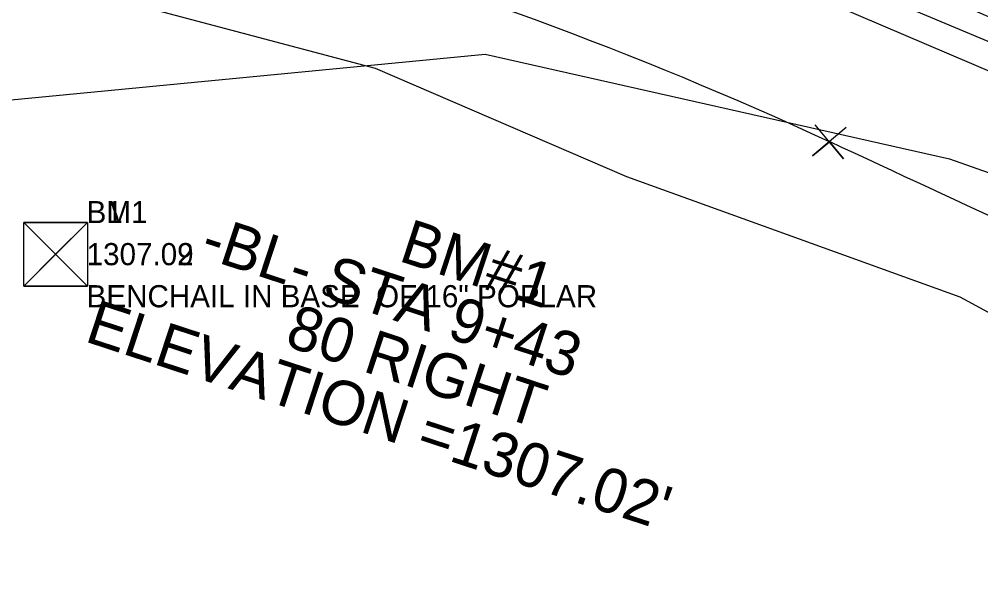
# Model space of a CAD drawing. Extents: x 1234385 to 1237843, y 694759 to 696635.
# Drawn here: x 1235013.1 to 1235121.7, y 695194.5 to 695257.9 of the extents above; entities that cross this region are included whole.
import ezdxf

# ---------------------------------------------------------------- set-up
doc = ezdxf.new("R2010")
doc.units = 0
for name, color, linetype in [('CTL Sheet Text', 7, 'Continuous'), ('CTL Vertical Benchmark CELL', 7, 'Continuous'), ('CTL Vertical Benchmark Cogo Comment', 7, 'Continuous'), ('CTL Vertical Benchmark Cogo Elevation', 7, 'Continuous'), ('CTL Vertical Benchmark Cogo Number', 7, 'Continuous'), ('Exist Horizontal Alignment', 7, 'Continuous'), ('Exist Hydro Jurisdictional Stream or Body of Water', 7, 'Continuous'), ('Exist Property Corner CELL', 7, 'Continuous'), ('Exist Right of Way Line', 7, 'Continuous'), ('Exist Roads EOP', 7, 'Continuous'), ('Exist Utilities Telephone UG Cable SUE LOS C', 7, 'Continuous'), ('Exist Vegetation Woods Line', 7, 'Continuous')]:
    doc.layers.add(name, color=color, linetype=linetype)

msp = doc.modelspace()

# ---------------------------------------------------------------- linework, layer by layer
at = {"layer": 'CTL Vertical Benchmark CELL'}
msp.add_line((1235017.19, 695231.36), (1235017.19, 695231.36), dxfattribs=at)
msp.add_line((1235017.19, 695231.36), (1235017.19, 695231.36), dxfattribs=at)
msp.add_lwpolyline([(1235013.59, 695234.95), (1235020.78, 695234.95), (1235020.78, 695227.76), (1235013.59, 695227.76)], close=True, dxfattribs=at)
msp.add_lwpolyline([(1235013.59, 695234.95), (1235020.78, 695234.95), (1235020.78, 695227.76), (1235013.59, 695227.76)], close=True, dxfattribs=at)
for points in [[(1235020.78, 695234.95), (1235013.59, 695227.76), (1235017.19, 695231.35), (1235020.78, 695227.76), (1235013.59, 695234.95)], [(1235017.19, 695231.35), (1235020.78, 695234.95), (1235013.59, 695234.95), (1235017.19, 695231.35)], [(1235020.78, 695234.95), (1235013.59, 695227.76), (1235017.19, 695231.35), (1235020.78, 695227.76), (1235013.59, 695234.95)], [(1235017.19, 695231.35), (1235020.78, 695234.95), (1235013.59, 695234.95), (1235017.19, 695231.35)], [(1235017.19, 695231.35), (1235013.59, 695227.76), (1235020.78, 695227.76), (1235017.19, 695231.35)], [(1235017.19, 695231.35), (1235013.59, 695227.76), (1235020.78, 695227.76), (1235017.19, 695231.35)]]:
    msp.add_lwpolyline(points, dxfattribs=at)
at = {"layer": 'Exist Horizontal Alignment'}
msp.add_arc((1232714.08, 690070.03), 5729.58, 64.20204, 65.20204, dxfattribs=at)
at = {"layer": 'Exist Hydro Jurisdictional Stream or Body of Water'}
for points in [[(1235024.44, 695280.43), (1235058.02, 695274.71), (1235089.92, 695266.04), (1235123.22, 695251.8), (1235172.11, 695226.53), (1235193.34, 695212.71), (1235213.17, 695197.45), (1235252.35, 695179.59), (1235273.06, 695163.48)], [(1235018.75, 695261.57), (1235053.27, 695252.38), (1235081.66, 695240.14), (1235119.35, 695226.52), (1235169.37, 695199.43), (1235188.12, 695189.81), (1235205.75, 695183.35), (1235242.09, 695153.73), (1235263.47, 695141.32)]]:
    msp.add_lwpolyline(points, dxfattribs=at)
at = {"layer": 'Exist Property Corner CELL'}
msp.add_line((1235104.59, 695244.06), (1235104.59, 695244.06), dxfattribs=at)
msp.add_lwpolyline([(1235106.51, 695245.67), (1235102.67, 695242.46), (1235104.59, 695244.06), (1235106.2, 695242.14), (1235102.99, 695245.98)], dxfattribs=at)
at = {"layer": 'Exist Right of Way Line'}
for centre, radius, start, end in [((1234916.92, 694837.86), 447.46, 65.202, 74.4376), ((1232714.08, 690070.03), 5699.58, 64.20204, 65.20204)]:
    msp.add_arc(centre, radius, start, end, dxfattribs=at)
at = {"layer": 'Exist Roads EOP'}
for points in [[(1234989.74, 695321.28), (1235032.63, 695310.76), (1235082.97, 695294.62), (1235134.25, 695274.48), (1235183.93, 695250.95), (1235232.11, 695225.68)], [(1234969.59, 695304.59), (1235025.45, 695292.96), (1235076.31, 695277.19), (1235126.22, 695256.57), (1235174.52, 695234.32), (1235222.25, 695208.99)]]:
    msp.add_spline(points, degree=3, dxfattribs=at)
at = {"layer": 'Exist Utilities Telephone UG Cable SUE LOS C'}
msp.add_lwpolyline([(1234556.88, 695335.53), (1234556.74, 695340.72), (1234570.65, 695340.51), (1234623.54, 695336.02), (1234680.23, 695326.9), (1234743, 695322.74), (1234798.61, 695317.57), (1234871.04, 695309.65), (1234972.12, 695299.54), (1235029.46, 695287.9), (1235091.91, 695268.26), (1235135.27, 695250.07), (1235195.38, 695220.09), (1235241.54, 695194.86), (1235279.05, 695173.58)], dxfattribs=at)
at = {"layer": 'Exist Vegetation Woods Line'}
msp.add_lwpolyline([(1234846.34, 695211.66), (1234862.97, 695243.02), (1234869.05, 695259.98), (1234914.47, 695262.54), (1234957.97, 695265.42), (1234988.67, 695246.54), (1235065.72, 695253.96), (1235118.17, 695242.12), (1235189.82, 695216.84), (1235231.72, 695188.68), (1235232.28, 695138.59), (1235209.33, 695099.95), (1235186.38, 695079.79)], dxfattribs=at)

# ---------------------------------------------------------------- texts
at = {"layer": 'CTL Sheet Text'}
for s, p in [('-BL- STA 9+43', (1235033.33, 695231.11)), ('BM#1', (1235055.8, 695230.64)), ("ELEVATION =1307.02'", (1235020.33, 695221.55)), ('80 RIGHT', (1235042.92, 695221.06))]:
    msp.add_text(s, height=5, rotation=341.8453, dxfattribs=at).set_placement(p)
at = {"layer": 'CTL Vertical Benchmark Cogo Comment'}
msp.add_text('BENCHAIL IN BASE  OF 16" POPLAR', height=2.5, dxfattribs=at).set_placement((1235020.69, 695225.36))
at = {"layer": 'CTL Vertical Benchmark Cogo Elevation'}
for s in ['1307.09', '1307.02']:
    msp.add_text(s, height=2.5, dxfattribs=at).set_placement((1235020.69, 695230.11))
at = {"layer": 'CTL Vertical Benchmark Cogo Number'}
for s in ['B1', 'BM1']:
    msp.add_text(s, height=2.5, dxfattribs=at).set_placement((1235020.69, 695234.86))

doc.saveas('drawing.dxf')
